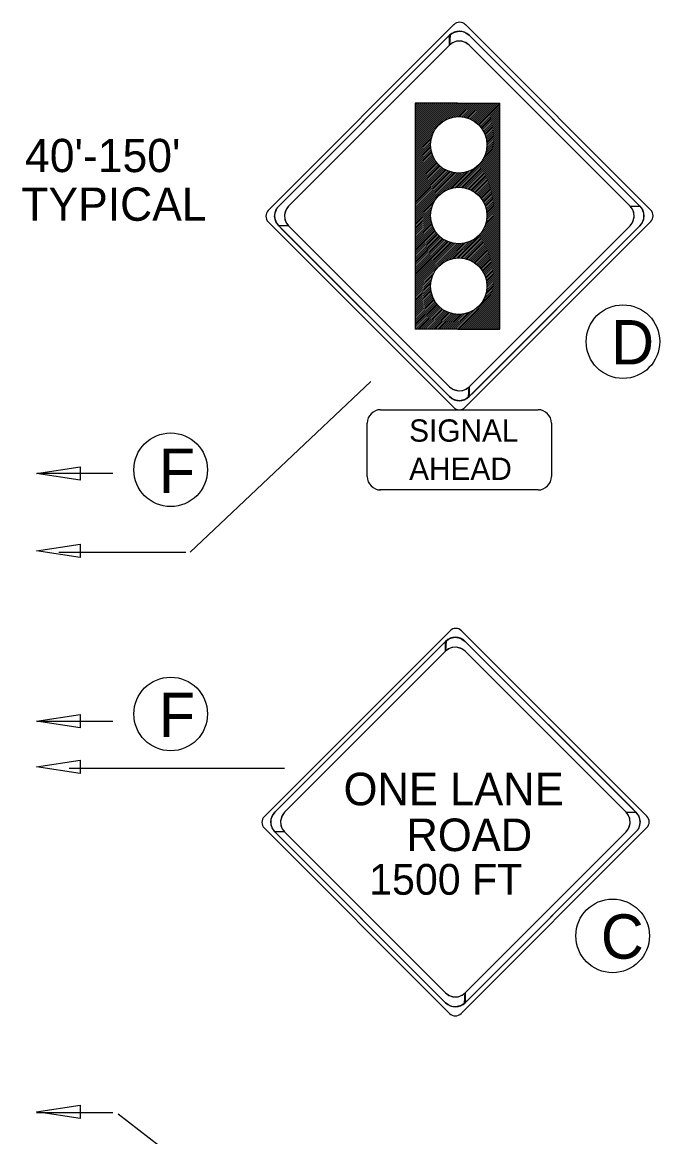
# Model space of a CAD drawing. Extents: x 1531.2 to 1538.6, y 1529.6 to 1539.7.
# Drawn here: x 1535.741 to 1536.891, y 1534.158 to 1536.168 of the extents above; entities that cross this region are included whole.
import ezdxf

# ---------------------------------------------------------------- set-up
doc = ezdxf.new("R2010")
doc.units = 0
for name, color, linetype in [('DETL-DIMS', 7, 'Continuous'), ('DETL-LINE', 7, 'Continuous'), ('DETL-NOTE', 7, 'Continuous')]:
    doc.layers.add(name, color=color, linetype=linetype)

msp = doc.modelspace()

# ---------------------------------------------------------------- linework, layer by layer
at = {"layer": 'DETL-DIMS'}
for p, q in [((1536.0434, 1535.2121), (1536.3694, 1535.5197)), ((1535.7673, 1535.3545), (1535.9038, 1535.3545)), ((1535.8065, 1535.2121), (1536.0357, 1535.2121)), ((1535.7673, 1534.9075), (1535.9038, 1534.9075)), ((1535.8254, 1534.8223), (1536.2139, 1534.8223)), ((1535.7664, 1534.2015), (1535.9038, 1534.2015)), ((1535.9135, 1534.1989), (1536.2418, 1533.9465))]:
    msp.add_line(p, q, dxfattribs=at)
for points in [[(1535.7664, 1535.3541), (1535.8449, 1535.3661), (1535.8449, 1535.3421)], [(1535.7664, 1535.2146), (1535.8449, 1535.2266), (1535.8449, 1535.2026)], [(1535.7664, 1534.9072), (1535.8449, 1534.9192), (1535.8449, 1534.8952)], [(1535.7664, 1534.8247), (1535.8449, 1534.8367), (1535.8449, 1534.8127)], [(1535.7664, 1534.2024), (1535.8449, 1534.2144), (1535.8449, 1534.1904)]]:
    msp.add_lwpolyline(points, close=True, dxfattribs=at)
at = {"layer": 'DETL-LINE'}
for p, q in [((1536.5197, 1536.1637), (1536.1846, 1535.8285)), ((1536.8749, 1535.8293), (1536.5405, 1536.1637)), ((1536.2035, 1535.8364), (1536.5116, 1536.1446)), ((1536.5471, 1536.1446), (1536.8553, 1535.8364)), ((1536.5116, 1536.1268), (1536.2212, 1535.8364)), ((1536.8375, 1535.8364), (1536.5471, 1536.1268)), ((1536.5263, 1536.0223), (1536.4498, 1536.0223)), ((1536.4498, 1536.0223), (1536.4498, 1535.6143)), ((1536.4498, 1535.9423), (1536.5298, 1536.0223)), ((1536.4498, 1535.9459), (1536.5262, 1536.0223)), ((1536.4498, 1535.9496), (1536.5226, 1536.0223)), ((1536.4498, 1535.9531), (1536.519, 1536.0223)), ((1536.4498, 1535.9567), (1536.5153, 1536.0223)), ((1536.4498, 1535.9603), (1536.5117, 1536.0223)), ((1536.4498, 1535.9639), (1536.5081, 1536.0223)), ((1536.4498, 1535.9675), (1536.5045, 1536.0223)), ((1536.4498, 1535.9712), (1536.501, 1536.0223)), ((1536.4498, 1535.9748), (1536.4973, 1536.0223)), ((1536.4498, 1535.9784), (1536.4937, 1536.0223)), ((1536.4498, 1535.9819), (1536.4901, 1536.0223)), ((1536.4498, 1535.9855), (1536.4865, 1536.0223)), ((1536.4498, 1535.9892), (1536.4829, 1536.0223)), ((1536.4498, 1535.9928), (1536.4793, 1536.0223)), ((1536.4498, 1535.9964), (1536.4757, 1536.0223)), ((1536.4498, 1536), (1536.4721, 1536.0223)), ((1536.4498, 1536.0036), (1536.4685, 1536.0223)), ((1536.4498, 1536.0073), (1536.4649, 1536.0223)), ((1536.4498, 1536.0109), (1536.4612, 1536.0223)), ((1536.4498, 1536.0144), (1536.4577, 1536.0223)), ((1536.4498, 1536.018), (1536.4541, 1536.0223)), ((1536.4498, 1536.0216), (1536.4505, 1536.0223)), ((1536.5011, 1535.9899), (1536.5334, 1536.0223)), ((1536.5086, 1535.9939), (1536.537, 1536.0223)), ((1536.5142, 1535.9958), (1536.5406, 1536.0223)), ((1536.5189, 1535.997), (1536.5442, 1536.0223)), ((1536.5232, 1535.9975), (1536.5478, 1536.0223)), ((1536.5263, 1536.0223), (1536.6028, 1536.0223)), ((1536.527, 1535.9979), (1536.5514, 1536.0223)), ((1536.5306, 1535.9978), (1536.555, 1536.0223)), ((1536.5339, 1535.9975), (1536.5587, 1536.0223)), ((1536.537, 1535.9971), (1536.5623, 1536.0223)), ((1536.5401, 1535.9965), (1536.5659, 1536.0223)), ((1536.5429, 1535.9957), (1536.5694, 1536.0223)), ((1536.5456, 1535.9949), (1536.573, 1536.0223)), ((1536.5482, 1535.9938), (1536.5767, 1536.0223)), ((1536.5507, 1535.9927), (1536.5803, 1536.0223)), ((1536.553, 1535.9914), (1536.5839, 1536.0223)), ((1536.5553, 1535.9901), (1536.5875, 1536.0223)), ((1536.5575, 1535.9887), (1536.5911, 1536.0223)), ((1536.5595, 1535.9872), (1536.5947, 1536.0223)), ((1536.5616, 1535.9855), (1536.5983, 1536.0223)), ((1536.5635, 1535.9838), (1536.6019, 1536.0223)), ((1536.5653, 1535.9821), (1536.6028, 1536.0196)), ((1536.6028, 1535.6143), (1536.6028, 1536.0223)), ((1536.567, 1535.9801), (1536.6028, 1536.016)), ((1536.5686, 1535.9781), (1536.6028, 1536.0124)), ((1536.5702, 1535.9761), (1536.6028, 1536.0087)), ((1536.5715, 1535.9739), (1536.6028, 1536.0051)), ((1536.5729, 1535.9716), (1536.6028, 1536.0015)), ((1536.5742, 1535.9692), (1536.6028, 1535.9979)), ((1536.5753, 1535.9668), (1536.6028, 1535.9944)), ((1536.5763, 1535.9642), (1536.6028, 1535.9908)), ((1536.5772, 1535.9615), (1536.6028, 1535.9871)), ((1536.5779, 1535.9586), (1536.6028, 1535.9835)), ((1536.5786, 1535.9556), (1536.6028, 1535.9799)), ((1536.4498, 1535.9387), (1536.4852, 1535.9741)), ((1536.4498, 1535.9351), (1536.4813, 1535.9665)), ((1536.4498, 1535.9315), (1536.4793, 1535.961)), ((1536.5773, 1535.9327), (1536.6028, 1535.9583)), ((1536.5785, 1535.9375), (1536.6028, 1535.9619)), ((1536.579, 1535.9525), (1536.6028, 1535.9763)), ((1536.5791, 1535.9417), (1536.6028, 1535.9655)), ((1536.5793, 1535.9491), (1536.6028, 1535.9727)), ((1536.5793, 1535.9456), (1536.6028, 1535.9691)), ((1536.4498, 1535.9279), (1536.4782, 1535.9563)), ((1536.4498, 1535.9243), (1536.4775, 1535.952)), ((1536.4498, 1535.9207), (1536.4773, 1535.9482)), ((1536.4498, 1535.9171), (1536.4774, 1535.9446)), ((1536.4498, 1535.9135), (1536.4776, 1535.9413)), ((1536.4498, 1535.9098), (1536.4781, 1535.9381)), ((1536.5257, 1535.8703), (1536.6028, 1535.9475)), ((1536.5293, 1535.8703), (1536.6028, 1535.9439)), ((1536.5327, 1535.8702), (1536.6028, 1535.9403)), ((1536.5715, 1535.9198), (1536.6028, 1535.951)), ((1536.5754, 1535.9272), (1536.6028, 1535.9547)), ((1536.4498, 1535.9062), (1536.4787, 1535.9351)), ((1536.4498, 1535.9027), (1536.4794, 1535.9323)), ((1536.4498, 1535.8991), (1536.4803, 1535.9296)), ((1536.4498, 1535.8955), (1536.4814, 1535.927)), ((1536.4498, 1535.8918), (1536.4825, 1535.9245)), ((1536.4498, 1535.8882), (1536.4837, 1535.9221)), ((1536.4498, 1535.8846), (1536.4851, 1535.9199)), ((1536.536, 1535.8697), (1536.6028, 1535.9367)), ((1536.539, 1535.8692), (1536.6028, 1535.933)), ((1536.5419, 1535.8685), (1536.6028, 1535.9294)), ((1536.5447, 1535.8676), (1536.6028, 1535.9258)), ((1536.5473, 1535.8667), (1536.6028, 1535.9222)), ((1536.5499, 1535.8656), (1536.6028, 1535.9186)), ((1536.4498, 1535.881), (1536.4865, 1535.9177)), ((1536.4498, 1535.8774), (1536.488, 1535.9156)), ((1536.4498, 1535.8737), (1536.4896, 1535.9136)), ((1536.4498, 1535.8702), (1536.4913, 1535.9117)), ((1536.4498, 1535.8666), (1536.4931, 1535.9099)), ((1536.4498, 1535.863), (1536.495, 1535.9082)), ((1536.4498, 1535.8594), (1536.4971, 1535.9066)), ((1536.4498, 1535.8557), (1536.4991, 1535.905)), ((1536.4498, 1535.8521), (1536.5013, 1535.9036)), ((1536.4498, 1535.8485), (1536.5036, 1535.9022)), ((1536.4498, 1535.8449), (1536.5059, 1535.901)), ((1536.4498, 1535.8414), (1536.5084, 1535.8999)), ((1536.4498, 1535.8378), (1536.511, 1535.8989)), ((1536.4498, 1535.8341), (1536.5137, 1535.898)), ((1536.5123, 1535.8678), (1536.5424, 1535.8978)), ((1536.5173, 1535.8691), (1536.548, 1535.8998)), ((1536.5217, 1535.8699), (1536.5554, 1535.9036)), ((1536.5522, 1535.8644), (1536.6028, 1535.915)), ((1536.5545, 1535.8631), (1536.6028, 1535.9114)), ((1536.5567, 1535.8617), (1536.6028, 1535.9078)), ((1536.5588, 1535.8602), (1536.6028, 1535.9042)), ((1536.5609, 1535.8586), (1536.6028, 1535.9006)), ((1536.4498, 1535.8305), (1536.5165, 1535.8973)), ((1536.4498, 1535.8269), (1536.5195, 1535.8966)), ((1536.4498, 1535.8233), (1536.5227, 1535.8962)), ((1536.4498, 1535.8161), (1536.5296, 1535.8959)), ((1536.4498, 1535.8197), (1536.526, 1535.8959)), ((1536.4967, 1535.8594), (1536.5335, 1535.8961)), ((1536.5063, 1535.8653), (1536.5377, 1535.8967)), ((1536.5628, 1535.8569), (1536.6028, 1535.8969)), ((1536.5646, 1535.8551), (1536.6028, 1535.8933)), ((1536.5664, 1535.8533), (1536.6028, 1535.8897)), ((1536.5681, 1535.8513), (1536.6028, 1535.8862)), ((1536.5696, 1535.8493), (1536.6028, 1535.8826)), ((1536.5711, 1535.8471), (1536.6028, 1535.8789)), ((1536.5725, 1535.8449), (1536.6028, 1535.8753)), ((1536.5737, 1535.8426), (1536.6028, 1535.8717)), ((1536.5749, 1535.8401), (1536.6028, 1535.8681)), ((1536.576, 1535.8376), (1536.6028, 1535.8645)), ((1536.5769, 1535.8349), (1536.6028, 1535.8609)), ((1536.4498, 1535.8125), (1536.4883, 1535.8509)), ((1536.4498, 1535.8089), (1536.4823, 1535.8414)), ((1536.5777, 1535.8321), (1536.6028, 1535.8573)), ((1536.5783, 1535.8292), (1536.6028, 1535.8537)), ((1536.5789, 1535.8261), (1536.6028, 1535.8501)), ((1536.5792, 1535.8228), (1536.6028, 1535.8465)), ((1536.5792, 1535.8157), (1536.6028, 1535.8393)), ((1536.5793, 1535.8193), (1536.6028, 1535.8429)), ((1536.4498, 1535.8053), (1536.4799, 1535.8353)), ((1536.4498, 1535.8017), (1536.4785, 1535.8303)), ((1536.4498, 1535.798), (1536.4778, 1535.826)), ((1536.4498, 1535.7945), (1536.4774, 1535.822)), ((1536.4498, 1535.7909), (1536.4773, 1535.8183)), ((1536.5243, 1535.7427), (1536.6028, 1535.8212)), ((1536.5281, 1535.7429), (1536.6028, 1535.8176)), ((1536.5733, 1535.7953), (1536.6028, 1535.8249)), ((1536.5762, 1535.8019), (1536.6028, 1535.8285)), ((1536.5778, 1535.807), (1536.6028, 1535.8321)), ((1536.5787, 1535.8116), (1536.6028, 1535.8357)), ((1536.1846, 1535.8078), (1536.519, 1535.4734)), ((1536.5116, 1535.4927), (1536.2035, 1535.8009)), ((1536.2212, 1535.8009), (1536.5116, 1535.5104)), ((1536.4498, 1535.7873), (1536.4775, 1535.8149)), ((1536.4498, 1535.7837), (1536.4779, 1535.8117)), ((1536.4498, 1535.78), (1536.4785, 1535.8087)), ((1536.4498, 1535.7764), (1536.4792, 1535.8058)), ((1536.4498, 1535.7728), (1536.48, 1535.803)), ((1536.4498, 1535.7692), (1536.481, 1535.8004)), ((1536.4498, 1535.7656), (1536.482, 1535.7979)), ((1536.5316, 1535.7427), (1536.6028, 1535.814)), ((1536.5348, 1535.7425), (1536.6028, 1535.8104)), ((1536.5379, 1535.7419), (1536.6028, 1535.8069)), ((1536.5397, 1535.4734), (1536.8749, 1535.8086)), ((1536.5409, 1535.7412), (1536.6028, 1535.8032)), ((1536.5437, 1535.7405), (1536.6028, 1535.7996)), ((1536.8553, 1535.8009), (1536.5471, 1535.4927)), ((1536.5471, 1535.5104), (1536.8375, 1535.8009)), ((1536.4498, 1535.762), (1536.4833, 1535.7954)), ((1536.4498, 1535.7584), (1536.4846, 1535.7931)), ((1536.4498, 1535.7548), (1536.4859, 1535.7909)), ((1536.4498, 1535.7512), (1536.4875, 1535.7888)), ((1536.4498, 1535.7476), (1536.4891, 1535.7868)), ((1536.4498, 1535.7439), (1536.4908, 1535.7849)), ((1536.4498, 1535.7403), (1536.4925, 1535.783)), ((1536.4498, 1535.7367), (1536.4944, 1535.7813)), ((1536.4498, 1535.7332), (1536.4963, 1535.7797)), ((1536.4498, 1535.7296), (1536.4983, 1535.7781)), ((1536.5464, 1535.7395), (1536.6028, 1535.796)), ((1536.5489, 1535.7385), (1536.6028, 1535.7924)), ((1536.5514, 1535.7373), (1536.6028, 1535.7888)), ((1536.5538, 1535.7361), (1536.6028, 1535.7851)), ((1536.556, 1535.7347), (1536.6028, 1535.7815)), ((1536.5581, 1535.7333), (1536.6028, 1535.7779)), ((1536.4498, 1535.7259), (1536.5005, 1535.7766)), ((1536.4498, 1535.7223), (1536.5028, 1535.7753)), ((1536.4498, 1535.7187), (1536.5051, 1535.774)), ((1536.4498, 1535.7151), (1536.5075, 1535.7728)), ((1536.4498, 1535.7115), (1536.51, 1535.7717)), ((1536.4498, 1535.7079), (1536.5127, 1535.7708)), ((1536.4498, 1535.7043), (1536.5155, 1535.77)), ((1536.4498, 1535.7007), (1536.5184, 1535.7693)), ((1536.4498, 1535.6971), (1536.5215, 1535.7688)), ((1536.4498, 1535.6935), (1536.5248, 1535.7685)), ((1536.4498, 1535.6863), (1536.5321, 1535.7685)), ((1536.4498, 1535.6899), (1536.5283, 1535.7683)), ((1536.5037, 1535.7365), (1536.5361, 1535.769)), ((1536.5103, 1535.7396), (1536.5406, 1535.7699)), ((1536.5157, 1535.7412), (1536.5459, 1535.7714)), ((1536.5201, 1535.7422), (1536.5524, 1535.7744)), ((1536.5601, 1535.7317), (1536.6028, 1535.7744)), ((1536.5621, 1535.7301), (1536.6028, 1535.7708)), ((1536.564, 1535.7283), (1536.6028, 1535.7671)), ((1536.5657, 1535.7265), (1536.6028, 1535.7635)), ((1536.5675, 1535.7246), (1536.6028, 1535.7599)), ((1536.569, 1535.7225), (1536.6028, 1535.7563)), ((1536.5706, 1535.7204), (1536.6028, 1535.7527)), ((1536.572, 1535.7182), (1536.6028, 1535.7491)), ((1536.5733, 1535.7159), (1536.6028, 1535.7455)), ((1536.5745, 1535.7136), (1536.6028, 1535.7419)), ((1536.5755, 1535.7111), (1536.6028, 1535.7383)), ((1536.5765, 1535.7084), (1536.6028, 1535.7347)), ((1536.5774, 1535.7057), (1536.6028, 1535.7311)), ((1536.5782, 1535.7028), (1536.6028, 1535.7275)), ((1536.5787, 1535.6997), (1536.6028, 1535.7239)), ((1536.5791, 1535.6965), (1536.6028, 1535.7203)), ((1536.4498, 1535.6827), (1536.4837, 1535.7165)), ((1536.4498, 1535.6791), (1536.4806, 1535.7098)), ((1536.4498, 1535.6755), (1536.4789, 1535.7045)), ((1536.4498, 1535.6719), (1536.4779, 1535.6999)), ((1536.5746, 1535.6704), (1536.6028, 1535.6987)), ((1536.5769, 1535.6763), (1536.6028, 1535.7022)), ((1536.5782, 1535.6812), (1536.6028, 1535.7058)), ((1536.5789, 1535.6855), (1536.6028, 1535.7094)), ((1536.5793, 1535.6931), (1536.6028, 1535.7167)), ((1536.5793, 1535.6895), (1536.6028, 1535.7131)), ((1536.4498, 1535.6682), (1536.4775, 1535.6959)), ((1536.4498, 1535.6646), (1536.4773, 1535.6921)), ((1536.4498, 1535.661), (1536.4774, 1535.6886)), ((1536.4498, 1535.6574), (1536.4777, 1535.6853)), ((1536.4498, 1535.6539), (1536.4782, 1535.6823)), ((1536.4498, 1535.6502), (1536.4789, 1535.6793)), ((1536.5258, 1535.6143), (1536.6028, 1535.6914)), ((1536.5294, 1535.6143), (1536.6028, 1535.6878)), ((1536.5329, 1535.6143), (1536.6028, 1535.6842)), ((1536.5365, 1535.6143), (1536.6028, 1535.6806)), ((1536.5401, 1535.6143), (1536.6028, 1535.677)), ((1536.5693, 1535.6615), (1536.6028, 1535.6951)), ((1536.4498, 1535.6466), (1536.4797, 1535.6765)), ((1536.4498, 1535.643), (1536.4807, 1535.6737)), ((1536.4498, 1535.6394), (1536.4817, 1535.6712)), ((1536.4498, 1535.6358), (1536.4829, 1535.6688)), ((1536.4498, 1535.6321), (1536.4841, 1535.6664)), ((1536.4498, 1535.6285), (1536.4855, 1535.6642)), ((1536.4498, 1535.6249), (1536.4869, 1535.6621)), ((1536.4498, 1535.6214), (1536.4885, 1535.66)), ((1536.4498, 1535.6178), (1536.4901, 1535.658)), ((1536.5437, 1535.6143), (1536.6028, 1535.6733)), ((1536.5474, 1535.6143), (1536.6028, 1535.6697)), ((1536.551, 1535.6143), (1536.6028, 1535.6662)), ((1536.5546, 1535.6143), (1536.6028, 1535.6626)), ((1536.5582, 1535.6143), (1536.6028, 1535.659)), ((1536.45, 1535.6143), (1536.4918, 1535.6562)), ((1536.4537, 1535.6143), (1536.4937, 1535.6544)), ((1536.4572, 1535.6143), (1536.4956, 1535.6527)), ((1536.4608, 1535.6143), (1536.4976, 1535.6511)), ((1536.4644, 1535.6143), (1536.4997, 1535.6496)), ((1536.468, 1535.6143), (1536.5019, 1535.6482)), ((1536.4717, 1535.6143), (1536.5042, 1535.6469)), ((1536.4753, 1535.6143), (1536.5066, 1535.6457)), ((1536.4789, 1535.6143), (1536.5091, 1535.6446)), ((1536.4825, 1535.6143), (1536.5117, 1535.6437)), ((1536.486, 1535.6143), (1536.5145, 1535.6427)), ((1536.4897, 1535.6143), (1536.5174, 1535.642)), ((1536.4933, 1535.6143), (1536.5204, 1535.6415)), ((1536.4969, 1535.6143), (1536.5237, 1535.641)), ((1536.5005, 1535.6143), (1536.5271, 1535.6409)), ((1536.5041, 1535.6143), (1536.5307, 1535.6409)), ((1536.5077, 1535.6143), (1536.5347, 1535.6413)), ((1536.5113, 1535.6143), (1536.539, 1535.6419)), ((1536.5149, 1535.6143), (1536.5439, 1535.6433)), ((1536.5185, 1535.6143), (1536.5498, 1535.6456)), ((1536.5221, 1535.6143), (1536.5587, 1535.6509)), ((1536.5618, 1535.6143), (1536.6028, 1535.6553)), ((1536.5654, 1535.6143), (1536.6028, 1535.6517)), ((1536.569, 1535.6143), (1536.6028, 1535.6481)), ((1536.5726, 1535.6143), (1536.6028, 1535.6445)), ((1536.5762, 1535.6143), (1536.6028, 1535.6409)), ((1536.5798, 1535.6143), (1536.6028, 1535.6373)), ((1536.5835, 1535.6143), (1536.6028, 1535.6337)), ((1536.5871, 1535.6143), (1536.6028, 1535.6301)), ((1536.5907, 1535.6143), (1536.6028, 1535.6265)), ((1536.5942, 1535.6143), (1536.6028, 1535.6229)), ((1536.5978, 1535.6143), (1536.6028, 1535.6193)), ((1536.5263, 1535.6143), (1536.4498, 1535.6143)), ((1536.5263, 1535.6143), (1536.6028, 1535.6143)), ((1536.6015, 1535.6143), (1536.6028, 1535.6157)), ((1536.3873, 1535.4691), (1536.6714, 1535.4691)), ((1536.3629, 1535.3487), (1536.3629, 1535.4446)), ((1536.6959, 1535.4446), (1536.6959, 1535.3487)), ((1536.6714, 1535.3243), (1536.3855, 1535.3243)), ((1536.5126, 1535.0703), (1536.1775, 1534.7351)), ((1536.8678, 1534.7359), (1536.5334, 1535.0703)), ((1536.1963, 1534.7429), (1536.5045, 1535.0511)), ((1536.5045, 1535.0333), (1536.2141, 1534.743)), ((1536.8304, 1534.7429), (1536.54, 1535.0333)), ((1536.5401, 1535.0511), (1536.8482, 1534.7429)), ((1536.1775, 1534.7144), (1536.5119, 1534.38)), ((1536.5326, 1534.38), (1536.8678, 1534.7151)), ((1536.5045, 1534.3992), (1536.1963, 1534.7074)), ((1536.2141, 1534.7074), (1536.5045, 1534.417)), ((1536.8482, 1534.7074), (1536.5401, 1534.3992)), ((1536.5401, 1534.417), (1536.8304, 1534.7074))]:
    msp.add_line(p, q, dxfattribs=at)
for points in [[(1536.2035, 1535.8364), (1536.5028, 1536.1357), (1536.5127, 1536.1456), (1536.5116, 1536.1268), (1536.2212, 1535.8364), (1536.2166, 1535.8301), (1536.2139, 1535.8208), (1536.2146, 1535.8123), (1536.217, 1535.8065), (1536.2212, 1535.8009), (1536.2035, 1535.8009), (1536.1983, 1535.808), (1536.1961, 1535.8177), (1536.1969, 1535.8248), (1536.1991, 1535.8306)], [(1536.5471, 1536.1445), (1536.8464, 1535.8452), (1536.8563, 1535.8353), (1536.8375, 1535.8364), (1536.5471, 1536.1268), (1536.5409, 1536.1314), (1536.5316, 1536.1341), (1536.5231, 1536.1333), (1536.5172, 1536.1311), (1536.5116, 1536.1268), (1536.5116, 1536.1445), (1536.5188, 1536.1496), (1536.5284, 1536.1519), (1536.5355, 1536.1511), (1536.5413, 1536.1489)], [(1536.8553, 1535.8009), (1536.556, 1535.5016), (1536.546, 1535.4916), (1536.5471, 1535.5104), (1536.8375, 1535.8008), (1536.8421, 1535.8071), (1536.8448, 1535.8164), (1536.8441, 1535.8249), (1536.8417, 1535.8307), (1536.8375, 1535.8364), (1536.8553, 1535.8364), (1536.8603, 1535.8292), (1536.8626, 1535.8195), (1536.8619, 1535.8124), (1536.8596, 1535.8066)], [(1536.5116, 1535.4927), (1536.2123, 1535.792), (1536.2023, 1535.8019), (1536.2212, 1535.8009), (1536.5115, 1535.5104), (1536.5178, 1535.5059), (1536.5271, 1535.5032), (1536.5357, 1535.5039), (1536.5415, 1535.5062), (1536.5471, 1535.5104), (1536.5471, 1535.4927), (1536.5399, 1535.4877), (1536.5303, 1535.4853), (1536.5232, 1535.4861), (1536.5174, 1535.4884)], [(1536.54, 1535.0511), (1536.8393, 1534.7518), (1536.8492, 1534.7419), (1536.8304, 1534.7429), (1536.5401, 1535.0333), (1536.5338, 1535.038), (1536.5245, 1535.0406), (1536.5159, 1535.0399), (1536.5101, 1535.0376), (1536.5045, 1535.0333), (1536.5045, 1535.0511), (1536.5117, 1535.0561), (1536.5213, 1535.0585), (1536.5284, 1535.0577), (1536.5342, 1535.0554)], [(1536.1963, 1534.7429), (1536.4957, 1535.0422), (1536.5056, 1535.0522), (1536.5045, 1535.0333), (1536.2141, 1534.743), (1536.2095, 1534.7367), (1536.2068, 1534.7274), (1536.2075, 1534.7189), (1536.2099, 1534.713), (1536.2141, 1534.7074), (1536.1963, 1534.7074), (1536.1913, 1534.7146), (1536.189, 1534.7243), (1536.1897, 1534.7313), (1536.1919, 1534.7372)], [(1536.8482, 1534.7074), (1536.5489, 1534.4081), (1536.5389, 1534.3982), (1536.54, 1534.417), (1536.8304, 1534.7074), (1536.835, 1534.7137), (1536.8377, 1534.7229), (1536.8369, 1534.7314), (1536.8346, 1534.7373), (1536.8304, 1534.7429), (1536.8482, 1534.7429), (1536.8532, 1534.7358), (1536.8555, 1534.7261), (1536.8548, 1534.719), (1536.8525, 1534.7132)], [(1536.5045, 1534.3993), (1536.2052, 1534.6985), (1536.1953, 1534.7085), (1536.2141, 1534.7074), (1536.5044, 1534.417), (1536.5107, 1534.4124), (1536.52, 1534.4098), (1536.5285, 1534.4105), (1536.5344, 1534.4127), (1536.54, 1534.417), (1536.54, 1534.3993), (1536.5328, 1534.3942), (1536.5232, 1534.3919), (1536.5161, 1534.3926), (1536.5103, 1534.3949)]]:
    msp.add_lwpolyline(points, close=True, dxfattribs=at)
for centre in [(1536.5283, 1535.9468), (1536.5283, 1535.8193), (1536.5283, 1535.6918)]:
    msp.add_circle(centre, 0.051, dxfattribs=at)
for centre, radius, start, end in [((1536.5301, 1536.1533), 0.0147, 45, 135), ((1536.5294, 1536.1268), 0.0251, 45, 135), ((1536.5293, 1536.109), 0.0251, 45, 135), ((1536.195, 1535.8182), 0.0147, 135, 225), ((1536.2212, 1535.8186), 0.0251, 135, 225), ((1536.239, 1535.8186), 0.0251, 135, 225), ((1536.8198, 1535.8186), 0.0251, 315, 45), ((1536.8376, 1535.8186), 0.0251, 315, 45), ((1536.8645, 1535.8189), 0.0147, 315, 45), ((1536.5294, 1535.5282), 0.0251, 225, 315), ((1536.5294, 1535.5104), 0.0251, 225, 315), ((1536.3874, 1535.4446), 0.0245, 90, 180), ((1536.5294, 1535.4838), 0.0147, 225, 315), ((1536.6714, 1535.4446), 0.0245, 0, 90), ((1536.3874, 1535.3488), 0.0245, 180, 270), ((1536.6714, 1535.3488), 0.0245, 270, 0), ((1536.523, 1535.0599), 0.0147, 45, 135), ((1536.5223, 1535.0334), 0.0251, 45, 135), ((1536.5222, 1535.0156), 0.0251, 45, 135), ((1536.1879, 1534.7247), 0.0147, 135, 225), ((1536.2141, 1534.7252), 0.0251, 135, 225), ((1536.2319, 1534.7252), 0.0251, 135, 225), ((1536.8127, 1534.7252), 0.0251, 315, 45), ((1536.8305, 1534.7252), 0.0251, 315, 45), ((1536.8574, 1534.7255), 0.0147, 315, 45), ((1536.5223, 1534.4348), 0.0251, 225, 315), ((1536.5223, 1534.417), 0.0251, 225, 315), ((1536.5223, 1534.3903), 0.0147, 225, 315)]:
    msp.add_arc(centre, radius, start, end, dxfattribs=at)
at = {"layer": 'DETL-NOTE'}
for centre in [(1536.8247, 1535.5919), (1536.0084, 1535.3607), (1536.0084, 1534.9202), (1536.8061, 1534.5199)]:
    msp.add_circle(centre, 0.0664, dxfattribs=at)

# ---------------------------------------------------------------- texts
at = {"layer": 'DETL-LINE'}
for s, height, p in [('SIGNAL  ', 0.04023, (1536.4388, 1535.4114)), ('AHEAD', 0.04023, (1536.4388, 1535.3424)), ('ONE LANE', 0.05875, (1536.3205, 1534.7555)), ('ROAD', 0.05875, (1536.4339, 1534.6728)), ('1500 FT', 0.05549, (1536.3667, 1534.5941))]:
    msp.add_text(s, height=height, dxfattribs=at).set_placement(p)
at = {"layer": 'DETL-NOTE'}
for s, height, p in [("40'-150'", 0.06, (1535.7456, 1535.8977)), ('TYPICAL', 0.06, (1535.7388, 1535.8099)), ('D', 0.08, (1536.8036, 1535.5508)), ('F', 0.08, (1535.9872, 1535.3191)), ('F', 0.08, (1535.9872, 1534.8787)), ('C', 0.08, (1536.7849, 1534.4787))]:
    msp.add_text(s, height=height, dxfattribs=at).set_placement(p)

doc.saveas('drawing.dxf')
